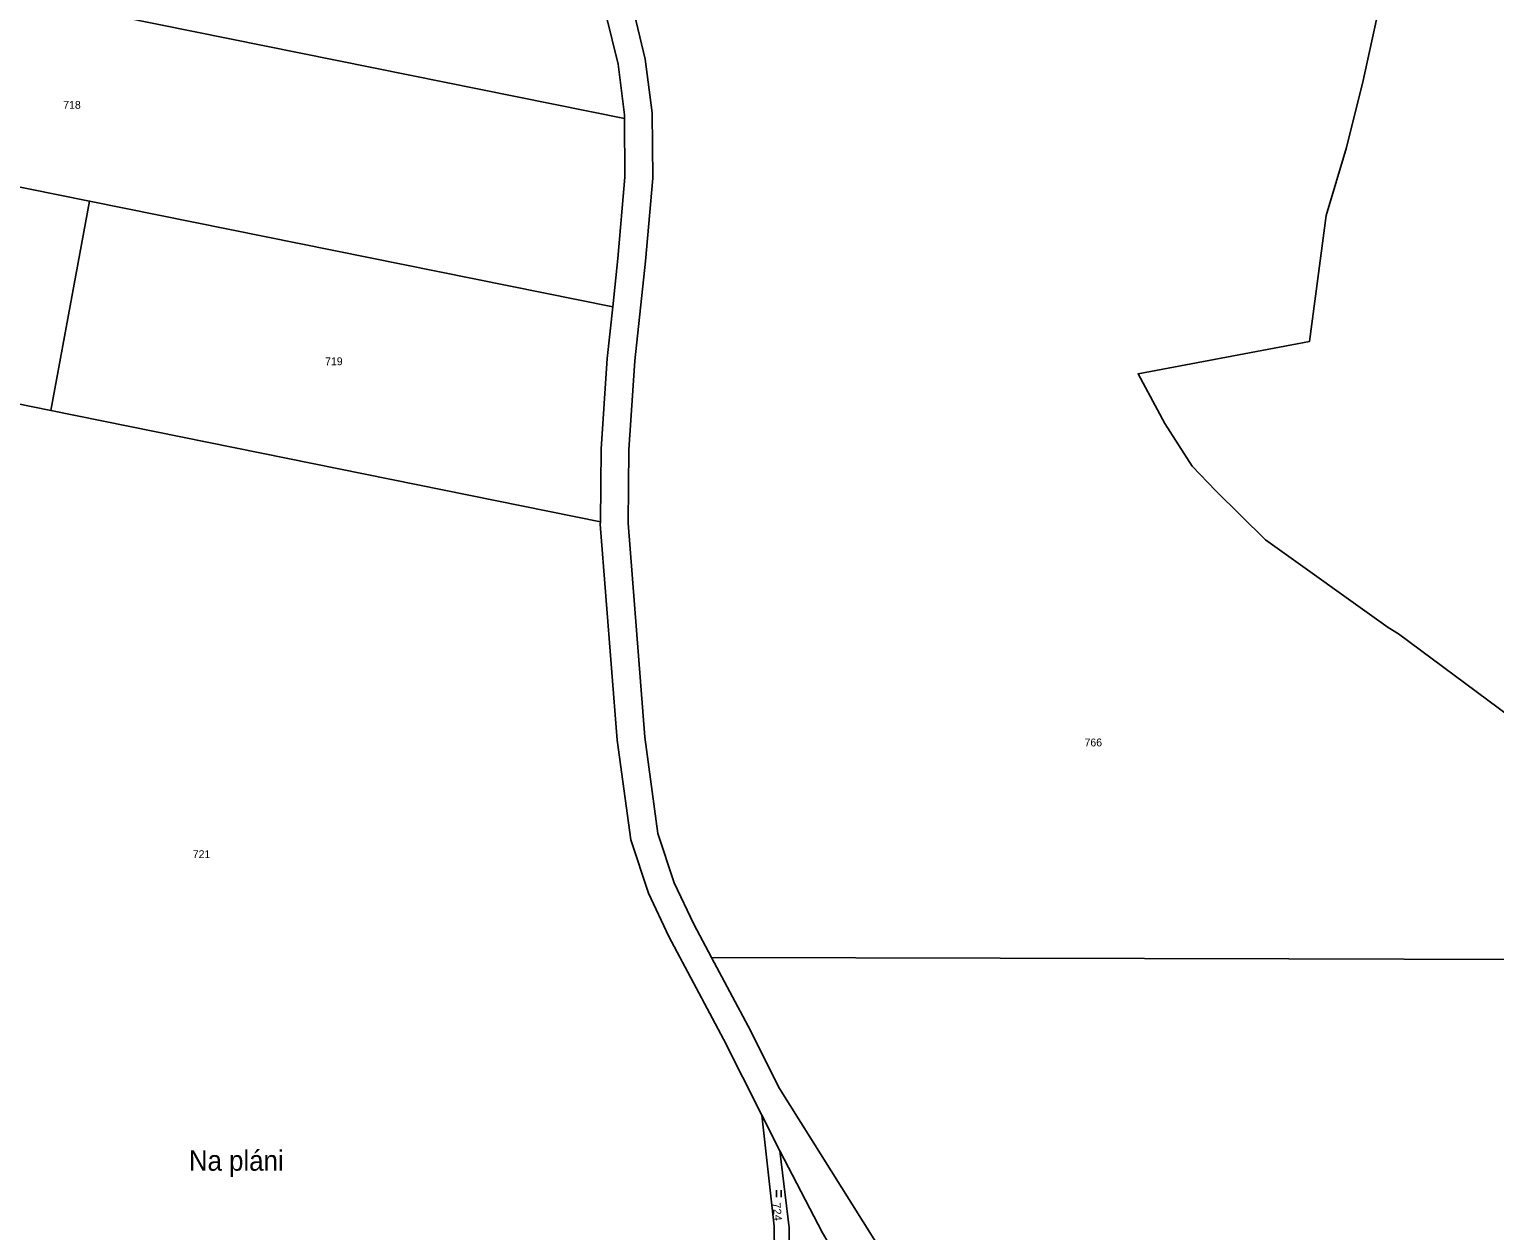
# Model space of a CAD drawing. Extents: x -754445 to -751443, y -1030748 to -1028224.
# Drawn here: x -752358.5 to -752041.3, y -1029657.7 to -1029397.6 of the extents above; entities that cross this region are included whole.
import ezdxf
from ezdxf.enums import TextEntityAlignment as Align

# ---------------------------------------------------------------- set-up
doc = ezdxf.new("R2010")
doc.units = 0
doc.header["$LTSCALE"] = 0.68
for name, color, linetype, lineweight in [('1', 7, 'Continuous', 25), ('3', 7, 'Continuous', 25), ('7', 7, 'Continuous', 13)]:
    doc.layers.add(name, color=color, linetype=linetype, lineweight=lineweight)
doc.layers.add('2', color=7, linetype='Continuous')

msp = doc.modelspace()

# ---------------------------------------------------------------- linework, layer by layer
at = {"layer": '1'}
for p, q in [((-752457.85, -1029459.12), (-752353.87, -1029480.15)), ((-752196.03, -1029640.38), (-752199.93, -1029632.66))]:
    msp.add_line(p, q, dxfattribs=at)
for points in [[(-752257.65, -1029298.65), (-752250.74, -1029317.42), (-752243.68, -1029341.84), (-752236.62, -1029367.09), (-752227.98, -1029392.65), (-752225.17, -1029404.06), (-752223.71, -1029415.73), (-752223.57, -1029429.84), (-752225.16, -1029447.79), (-752227.44, -1029469.4), (-752228.76, -1029488.65), (-752228.91, -1029504.56), (-752225.26, -1029550.87), (-752222.45, -1029571.71), (-752218.92, -1029582.35), (-752214.69, -1029591.3), (-752210.85, -1029598.51)], [(-752463.44, -1029369.74), (-752346.57, -1029393.35), (-752229.69, -1029416.96)], [(-751960.86, -1029599.16), (-751987.19, -1029578.43), (-752009.32, -1029561.85), (-752030.66, -1029551.79), (-752062.07, -1029528.51), (-752064.34, -1029527.13), (-752090.89, -1029508.1), (-752101.61, -1029497.51), (-752106.76, -1029492.22), (-752112.68, -1029482.96), (-752118.49, -1029472.18), (-752081.35, -1029465.17), (-752077.74, -1029437.96), (-752073.32, -1029423.23), (-752069.75, -1029408.73), (-752063.85, -1029381.61)], [(-752229.69, -1029416.96), (-752229.7, -1029416.13), (-752231.08, -1029405.16), (-752233.75, -1029394.33), (-752233.96, -1029393.72)], [(-752469.05, -1029409.85), (-752345.49, -1029434.81), (-752232.23, -1029457.69)], [(-752232.23, -1029457.69), (-752231.13, -1029447.21), (-752229.57, -1029429.6), (-752229.69, -1029416.96)], [(-752345.49, -1029434.81), (-752353.87, -1029480.15), (-752234.9, -1029504.2)], [(-752234.9, -1029504.2), (-752234.76, -1029488.41), (-752233.41, -1029468.88), (-752232.23, -1029457.69)], [(-752199.93, -1029632.66), (-752208.23, -1029616.19), (-752220.05, -1029593.99), (-752224.5, -1029584.58), (-752228.32, -1029573.07), (-752231.23, -1029551.51), (-752234.91, -1029504.77), (-752234.9, -1029504.2)], [(-752210.85, -1029598.51), (-752085.86, -1029598.84), (-751960.86, -1029599.16)], [(-752210.85, -1029598.51), (-752202.9, -1029613.43), (-752196.1, -1029626.91), (-752164.5, -1029677.22), (-752141.8, -1029712.13), (-752130.09, -1029731.01), (-752122.07, -1029746.38), (-752110.76, -1029772.03), (-752103.34, -1029794.29), (-752097.44, -1029818.68), (-752093.44, -1029845.4), (-752091.89, -1029870.03), (-752090.2, -1029912.61), (-752088.45, -1029951.67), (-752086.73, -1029991.22), (-752087.26, -1030044.65), (-752087.79, -1030063.79), (-752090.75, -1030119.86), (-752093.21, -1030149.03)], [(-752197.14, -1029668.36), (-752197.25, -1029656.71), (-752199.93, -1029632.66)], [(-752150.54, -1029720.06), (-752186.84, -1029658.11), (-752196.03, -1029640.38)], [(-752193.96, -1029668.43), (-752194, -1029657.07), (-752196.03, -1029640.38)]]:
    msp.add_lwpolyline(points, dxfattribs=at)
at = {"layer": '3'}
for p, q in [((-752196.751, -1029650.4), (-752196.751, -1029648.9)), ((-752195.75, -1029650.4), (-752195.75, -1029648.9))]:
    msp.add_line(p, q, dxfattribs=at)

# ---------------------------------------------------------------- texts
at = {"layer": '2'}
for s, p in [('718', (-752349.309, -1029414.836)), ('719', (-752292.599, -1029470.336)), ('766', (-752128.169, -1029552.846)), ('721', (-752321.259, -1029577.026))]:
    msp.add_text(s, height=1.7, dxfattribs=at).set_placement(p, align=Align.CENTER)
at = {"layer": '2', "width": 1.05}
msp.add_text('724', height=1.7, rotation=275, dxfattribs=at).set_placement((-752197.4365, -1029653.6329), align=Align.CENTER)
at = {"layer": '7', "width": 0.95}
msp.add_text('Na pláni', height=4.4, dxfattribs=at).set_placement((-752323.99, -1029644.69))

doc.saveas('drawing.dxf')
